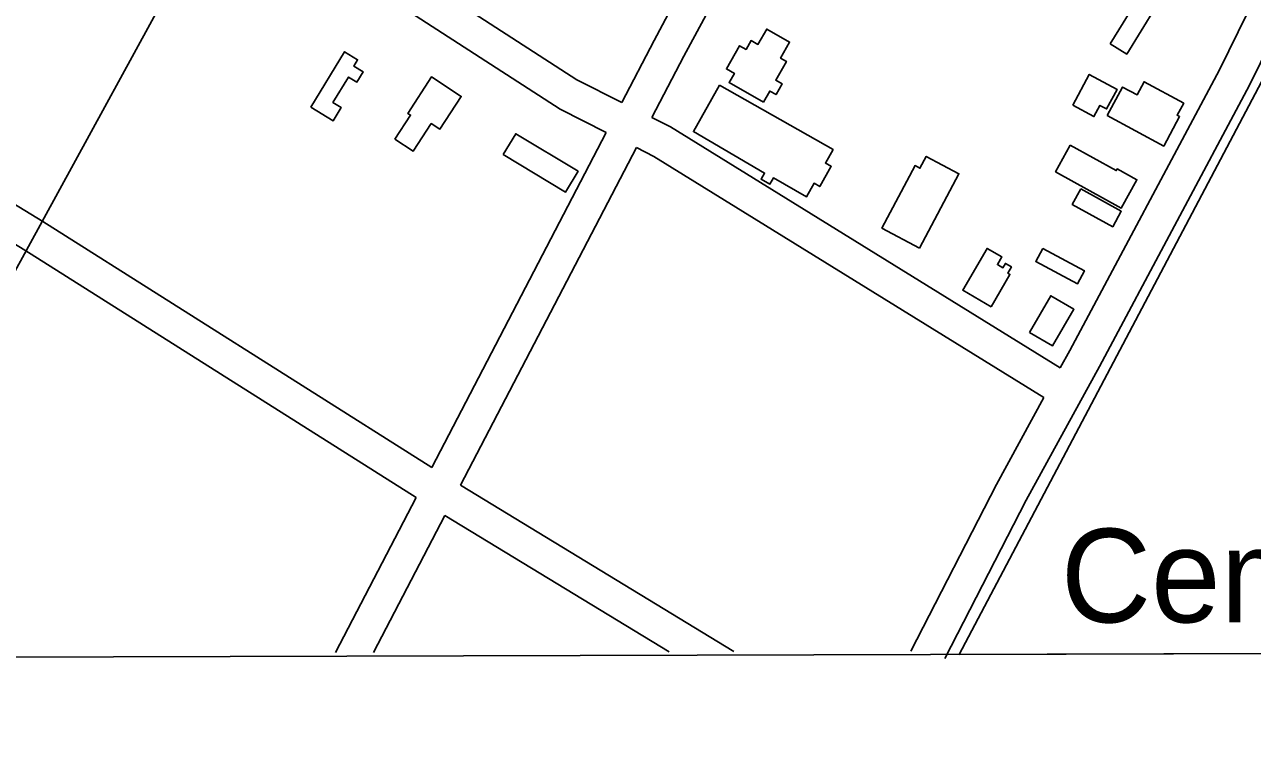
# Model space of a CAD drawing. Extents: x 3361039 to 3398939, y 576572 to 602007.
# Drawn here: x 3389671 to 3390761, y 581957 to 582586 of the extents above; entities that cross this region are included whole.
import ezdxf

# ---------------------------------------------------------------- set-up
doc = ezdxf.new("R2010")
doc.units = 0
for name, color, linetype in [('V-BLDG-OTLN', 7, 'Continuous'), ('V-GRID-FRAM', 7, 'Continuous'), ('V-ROAD-CNTR', 7, 'Continuous'), ('V-SITE-OTLN', 7, 'Continuous'), ('V-SITE-OTLN-IDEN', 7, 'Continuous')]:
    doc.layers.add(name, color=color, linetype=linetype)

msp = doc.modelspace()

# ---------------------------------------------------------------- linework, layer by layer
at = {"layer": 'V-BLDG-OTLN'}
for points in [[(3390634.6, 582568.9), (3390660.1, 582610.1), (3390674.9, 582601), (3390649.3, 582559.7)], [(3390326.9, 582517), (3390296.4, 582534.4), (3390301.1, 582542.6), (3390294, 582546.6), (3390305.7, 582567.1), (3390311.4, 582563.8), (3390315.9, 582571.7), (3390322, 582568.2), (3390329.8, 582581.9), (3390350.1, 582570.3), (3390342, 582556.1), (3390347.2, 582553.2), (3390337.7, 582536.5), (3390343.4, 582533.3), (3390338, 582523.7), (3390332.5, 582526.8)], [(3389925, 582512.7), (3389955, 582561.8), (3389966.6, 582554.6), (3389963.2, 582549), (3389971.6, 582543.9), (3389965.9, 582534.8), (3389958.5, 582539.3), (3389944.7, 582516.8), (3389952.1, 582512.3), (3389944.9, 582500.5)], [(3389999.7, 582484.1), (3390013.6, 582505.5), (3390011.1, 582507.1), (3390032.1, 582539.4), (3390058.5, 582522.2), (3390039.6, 582493.1), (3390031.9, 582498.1), (3390015.9, 582473.6)], [(3390601.4, 582514.3), (3390616.1, 582541.6), (3390640.8, 582528.3), (3390631.5, 582511), (3390625.5, 582514.2), (3390620.2, 582504.2)], [(3390287.9, 582532), (3390388.6, 582474.9), (3390381.9, 582463), (3390387, 582460.2), (3390376.8, 582442.2), (3390371.8, 582445.1), (3390365.1, 582433.1), (3390335.7, 582449.8), (3390332.6, 582444.3), (3390324.8, 582448.7), (3390327.9, 582454.1), (3390264.7, 582491)], [(3390631.9, 582505.1), (3390645.6, 582530.4), (3390658.5, 582523.4), (3390664.8, 582535.1), (3390699.9, 582516.1), (3390694.1, 582505.4), (3390696.3, 582504.2), (3390682.2, 582478)], [(3390095.8, 582470.5), (3390107, 582489), (3390162.3, 582455.7), (3390151.1, 582437.1)], [(3390599, 582478.8), (3390640, 582456.3), (3390640.9, 582457.8), (3390658.3, 582448.2), (3390644.5, 582423.1), (3390586.1, 582455.3)], [(3390465.5, 582387.5), (3390432, 582405.3), (3390461.4, 582460.7), (3390465.7, 582458.4), (3390471.3, 582468.9), (3390500.4, 582453.5)], [(3390608.5, 582440), (3390644.5, 582420.2), (3390636.9, 582406.5), (3390601, 582426.3)], [(3390528.9, 582335.4), (3390503.8, 582350.1), (3390525.4, 582387.3), (3390538.6, 582379.7), (3390534.6, 582372.9), (3390539.4, 582370.1), (3390541.7, 582374), (3390546.9, 582370.9), (3390543.7, 582365.4), (3390545.7, 582364.2)], [(3390574.8, 582387.2), (3390611.8, 582367.4), (3390605.6, 582355.8), (3390568.6, 582375.6)], [(3390562.9, 582312.8), (3390581.9, 582345.3), (3390602.4, 582333.3), (3390583.3, 582300.8)]]:
    msp.add_lwpolyline(points, close=True, dxfattribs=at)
at = {"layer": 'V-GRID-FRAM'}
msp.add_lwpolyline([(3365114.8, 600140.3), (3396720.3, 600227.7), (3396778.5, 582044.3), (3365157.1, 581956.9), (3365114.8, 600140.3)], dxfattribs=at)
at = {"layer": 'V-ROAD-CNTR'}
for points in [[(3390766.6, 584361.9), (3390672.6, 584186.8), (3390635.6, 584118.4), (3390437.2, 583755.7), (3390398.7, 583691.2), (3390243.7, 583416.2), (3390208.3, 583351.6), (3390058.1, 583079.9), (3390026.6, 583013.6), (3389871.2, 582747.7), (3389837.7, 582687.9), (3389660.5, 582363.6), (3389513.4, 582106.3), (3389465.7, 582027.3)], [(3390201.1, 582516.8), (3390161.2, 582536.8), (3389882.8, 582717), (3389534.4, 582936.2), (3389515.7, 582947.6)], [(3390187.2, 582490.2), (3390146.3, 582510.8), (3389866.6, 582691.7), (3389518.6, 582910.7), (3389499.7, 582922.3)], [(3390368.3, 582831.3), (3390347.1, 582791.4), (3390297.2, 582698.1), (3390247.4, 582604.7), (3390229.8, 582571.8)], [(3390394, 582815.7), (3390373.5, 582777.3), (3390323.7, 582683.9), (3390273.8, 582590.6), (3390256.2, 582557.7)], [(3389320.6, 582639.3), (3389545.4, 582497.4), (3389687.1, 582411.3), (3390032.4, 582193)], [(3389304.6, 582614), (3389529.7, 582471.9), (3389671.3, 582385.8), (3390018.5, 582166.3)], [(3390797.7, 582612.4), (3390758.3, 582532), (3390625.1, 582282.5), (3390560.1, 582163.8), (3390488, 582023.4)], [(3390756.4, 582596.2), (3390731.6, 582545.7), (3390598.7, 582296.8), (3390590.3, 582281.4)], [(3390229.7, 582571.7), (3390201.1, 582516.8)], [(3390256.3, 582557.8), (3390227.9, 582503.3)], [(3390590.3, 582281.4), (3390244.2, 582495.1), (3390227.9, 582503.3)], [(3390187.2, 582490.2), (3390032.4, 582193)], [(3390214, 582476.7), (3390057.9, 582177.1)], [(3390575.8, 582255), (3390229.5, 582468.9), (3390214, 582476.7)], [(3390575.8, 582255), (3390533.6, 582177.8), (3390457.7, 582030)], [(3390057.9, 582177.1), (3390300.5, 582029.6)], [(3390018.5, 582166.3), (3389946.8, 582028.6)], [(3390044.1, 582150.4), (3389980.6, 582028.7)], [(3390044.1, 582150.4), (3390243, 582029.4)]]:
    msp.add_lwpolyline(points, dxfattribs=at)
at = {"layer": 'V-SITE-OTLN'}
for p, q in [((3390500.7, 582027), (3390790.3, 582575.9)), ((3390889.5, 582028.1), (3390500.7, 582027))]:
    msp.add_line(p, q, dxfattribs=at)

# ---------------------------------------------------------------- texts
at = {"layer": 'V-SITE-OTLN-IDEN'}
msp.add_text('Cem.', height=83, dxfattribs=at).set_placement((3390590.8, 582055.5))

doc.saveas('drawing.dxf')
